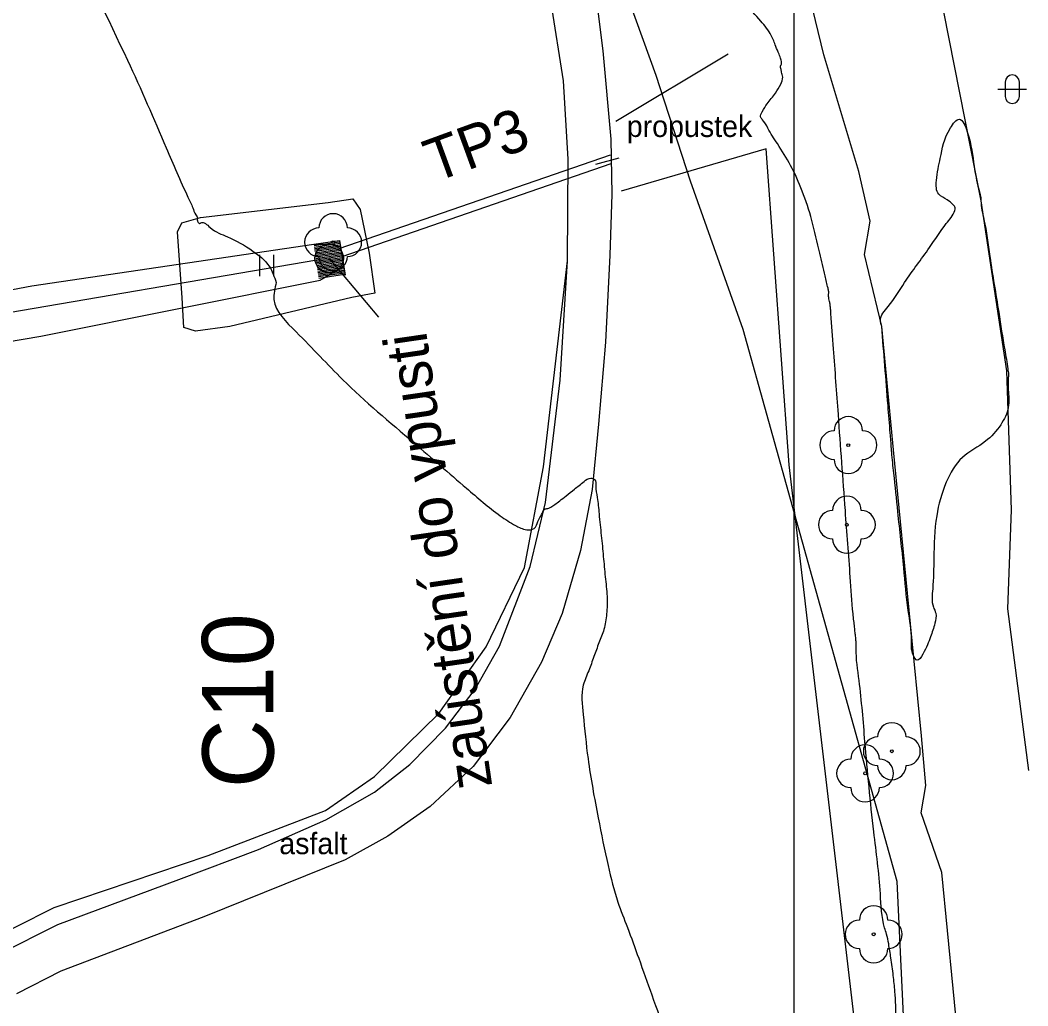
# Model space of a CAD drawing. Extents: x -478102 to -473059, y -1117705 to -1114104.
# Drawn here: x -476236.6 to -476165.9, y -1117084.2 to -1117015 of the extents above; entities that cross this region are included whole.
import ezdxf

# ---------------------------------------------------------------- set-up
doc = ezdxf.new("R2010")
doc.units = 0
for name, color, linetype in [('BodoveZnackySachtaKanalizacni', 7, 'Continuous'), ('cestn___p____kop_n__vrh', 7, 'Continuous'), ('el_vedeni__VN', 7, 'Continuous'), ('HladinaVodnihoToku', 7, 'Continuous'), ('HranaTerennihoUtvaru', 7, 'Continuous'), ('ObPÚ', 7, 'Continuous'), ('OstatniRozhrani', 7, 'Continuous'), ('POLYGONY_SITUACE_PO', 7, 'Continuous'), ('PopisneZnackyKultura', 7, 'Continuous'), ('PopisObjektu', 7, 'Continuous'), ('PopisPovrchu', 7, 'Continuous'), ('RozhraniKultur', 7, 'Continuous'), ('RozhraniVozovky', 7, 'Continuous'), ('TP _navrh', 7, 'Continuous'), ('TP_HS', 7, 'Continuous'), ('Vrstevnice_vedlejsi', 7, 'Continuous'), ('ZnackyStromu', 7, 'Continuous')]:
    doc.layers.add(name, color=color, linetype=linetype)

msp = doc.modelspace()

# ---------------------------------------------------------------- linework, layer by layer
for p, q in [((-476214.237, -1117031.047), (-476195.209, -1117024.475)), ((-476214.041, -1117031.614), (-476195.148, -1117025.088)), ((-476216.022, -1117030.757), (-476214.226, -1117030.492)), ((-476216.022, -1117030.757), (-476214.944, -1117030.754)), ((-476216.022, -1117030.757), (-476214.944, -1117030.754)), ((-476216.008, -1117030.856), (-476214.211, -1117030.591)), ((-476215.993, -1117030.955), (-476214.197, -1117030.69)), ((-476215.978, -1117031.054), (-476214.182, -1117030.789)), ((-476215.964, -1117031.153), (-476214.168, -1117030.888)), ((-476215.949, -1117031.252), (-476214.153, -1117030.986)), ((-476215.935, -1117031.351), (-476214.138, -1117031.085)), ((-476215.92, -1117031.449), (-476214.124, -1117031.184)), ((-476215.905, -1117031.548), (-476214.109, -1117031.283)), ((-476215.891, -1117031.647), (-476214.095, -1117031.382)), ((-476215.876, -1117031.746), (-476214.08, -1117031.481)), ((-476215.862, -1117031.845), (-476214.065, -1117031.58)), ((-476215.847, -1117031.944), (-476214.051, -1117031.679)), ((-476215.832, -1117032.043), (-476214.036, -1117031.778)), ((-476215.818, -1117032.142), (-476214.022, -1117031.877)), ((-476215.803, -1117032.241), (-476214.007, -1117031.976)), ((-476215.789, -1117032.34), (-476213.992, -1117032.075)), ((-476215.774, -1117032.439), (-476213.978, -1117032.174)), ((-476215.759, -1117032.538), (-476213.963, -1117032.273)), ((-476215.745, -1117032.637), (-476213.949, -1117032.371)), ((-476214.944, -1117031.754), (-476211.472, -1117035.864)), ((-476215.73, -1117032.736), (-476213.934, -1117032.47)), ((-476215.715, -1117032.834), (-476213.919, -1117032.569)), ((-476215.701, -1117032.933), (-476213.905, -1117032.668)), ((-476215.686, -1117033.032), (-476213.89, -1117032.767)), ((-476215.672, -1117033.131), (-476213.876, -1117032.866)), ((-476215.571, -1117033.275), (-476214.35, -1117032.58)), ((-476215.571, -1117033.275), (-476214.35, -1117032.58))]:
    msp.add_line(p, q)
at = {"layer": 'BodoveZnackySachtaKanalizacni'}
msp.add_circle((-476214.944, -1117031.754), 1, dxfattribs=at)
msp.add_circle((-476214.944, -1117031.754), 1, dxfattribs=at)
msp.add_circle((-476214.944, -1117031.754), 1, dxfattribs=at)
msp.add_circle((-476214.944, -1117031.754), 1, dxfattribs=at)
at = {"layer": 'cestn___p____kop_n__vrh'}
msp.add_line((-476214.226, -1117030.492), (-476213.83, -1117032.921), dxfattribs=at)
msp.add_lwpolyline([(-476182.335, -1117180.282), (-476602.335, -1117180.282), (-476602.335, -1116586.282), (-476182.335, -1116586.282)], close=True, dxfattribs=at)
at = {"layer": 'el_vedeni__VN'}
for points in [[(-476235.819, -1117033.671), (-476216.022, -1117030.757)], [(-476255.471, -1117037.386), (-476235.819, -1117033.671)], [(-476235.187, -1117037.196), (-476215.571, -1117033.275)], [(-476254.906, -1117040.545), (-476235.187, -1117037.196)]]:
    msp.add_lwpolyline(points, dxfattribs=at)
at = {"layer": 'HladinaVodnihoToku'}
for points in [[(-476230.693, -1116889.189), (-476228.825, -1116902.805), (-476226.997, -1116912.134), (-476222.681, -1116925.337), (-476220.229, -1116932.601), (-476216.175, -1116939.113), (-476212.858, -1116942.625), (-476205.972, -1116953.141), (-476203.252, -1116954.891), (-476199.271, -1116960.088), (-476194.333, -1116968.049), (-476189.738, -1116975.171), (-476186.133, -1116982.38), (-476183.739, -1116986.147), (-476182.486, -1116989.695), (-476180.477, -1116994.376), (-476178.089, -1116997.289), (-476174.589, -1117005.739), (-476171.819, -1117014.439), (-476169.214, -1117027.705), (-476167.401, -1117039.631), (-476167.078, -1117049.404), (-476167.323, -1117056.351), (-476165.871, -1117067.691)], [(-476165.052, -1117135.383), (-476166.552, -1117122.432), (-476167.831, -1117116.835), (-476168.995, -1117106.978), (-476170.029, -1117098.738), (-476170.701, -1117095.145), (-476170.746, -1117087.056), (-476171.949, -1117074.832), (-476173.391, -1117070.652), (-476173.059, -1117068.741), (-476173.366, -1117065.264), (-476174.142, -1117057.395), (-476175.337, -1117045.193), (-476176.15, -1117036.518), (-476177.362, -1117031.476), (-476176.964, -1117029.141), (-476177.777, -1117025.659), (-476180.222, -1117017.465), (-476181.969, -1117010.204)]]:
    msp.add_lwpolyline(points, dxfattribs=at)
at = {"layer": 'HranaTerennihoUtvaru'}
for points in [[(-476186.94, -1117017.41), (-476194.82, -1117022.15)], [(-476178.08, -1117085.22), (-476182.65, -1117046.23), (-476184.28, -1117024.06), (-476194.45, -1117027.03)]]:
    msp.add_lwpolyline(points, dxfattribs=at)
at = {"layer": 'ObPÚ'}
msp.add_lwpolyline([(-476159.5, -1117192.77), (-476224.13, -1117203.13), (-476225.41, -1117191.08), (-476226.67, -1117162.34), (-476231.32, -1117146.23), (-476236.27, -1117130.89), (-476197.93, -1117123.85), (-476173.05, -1117118.52), (-476175.07, -1117075.48), (-476185.89, -1117036.74), (-476189.59, -1117026.33), (-476192, -1117018.92), (-476203.93, -1116985.93)], dxfattribs=at)
at = {"layer": 'OstatniRozhrani'}
msp.add_lwpolyline([(-476194.62, -1117024.71), (-476196.246, -1117025.164)], dxfattribs=at)
at = {"layer": 'POLYGONY_SITUACE_PO'}
msp.add_lwpolyline([(-476215.821, -1117031.882), (-476288.898, -1117044.364)], dxfattribs=at)
at = {"layer": 'PopisneZnackyKultura'}
for p, q in [((-476167.506, -1117019.386), (-476167.506, -1117020.386)), ((-476166.506, -1117019.386), (-476166.506, -1117020.386)), ((-476168.006, -1117019.886), (-476166.006, -1117019.886)), ((-476219.82, -1117032.999), (-476219.82, -1117031.499)), ((-476218.82, -1117032.999), (-476218.82, -1117031.499))]:
    msp.add_line(p, q, dxfattribs=at)
for centre, start, end in [((-476166.998, -1117019.378), 0, 180), ((-476166.998, -1117020.378), 180, 0)]:
    msp.add_arc(centre, 0.5, start, end, dxfattribs=at)
at = {"layer": 'RozhraniKultur'}
msp.add_lwpolyline([(-476225.593, -1117029.883), (-476225.296, -1117029.248), (-476223.977, -1117028.88), (-476215.019, -1117027.833), (-476213.274, -1117027.562), (-476212.764, -1117028.324), (-476212.138, -1117031.392), (-476211.741, -1117034.183), (-476213.357, -1117034.486), (-476221.906, -1117036.536), (-476224.324, -1117036.868), (-476225.145, -1117036.604), (-476225.253, -1117034.523)], close=True, dxfattribs=at)
msp.add_lwpolyline([(-476326.155, -1117118.092), (-476289.536, -1117114.347), (-476268.698, -1117113.377), (-476254.616, -1117112.232), (-476253.368, -1117111.396), (-476254.26, -1117105.118), (-476253.444, -1117098.834), (-476252.052, -1117092.56), (-476249.674, -1117089.102), (-476247.41, -1117085.365), (-476243.552, -1117082.341), (-476239.642, -1117080.005), (-476234.251, -1117077.288), (-476223.428, -1117073.653), (-476215.212, -1117070.499), (-476211.753, -1117068.101), (-476207.257, -1117063.687), (-476203.922, -1117059.007), (-476201.245, -1117053.431), (-476199.908, -1117046.384), (-476198.206, -1117031.932)], dxfattribs=at)
at = {"layer": 'RozhraniVozovky'}
for points in [[(-476196.364, -1117012.13), (-476195.729, -1117017.189), (-476195.176, -1117023.395), (-476195.112, -1117027.233), (-476195.235, -1117031.513), (-476195.559, -1117037.637), (-476196.033, -1117043.394), (-476196.483, -1117047.979), (-476197.306, -1117052.252), (-476198.582, -1117056.674), (-476200.039, -1117060.081), (-476202.244, -1117063.965), (-476204.836, -1117067.407), (-476207.857, -1117070.218), (-476210.834, -1117072.302), (-476213.828, -1117073.953), (-476223.737, -1117077.95), (-476233.774, -1117081.756), (-476236.901, -1117083.35)], [(-476238.115, -1117080.557), (-476233.979, -1117078.501), (-476225.492, -1117075.329), (-476219.895, -1117073.227), (-476215.189, -1117071.158), (-476211.766, -1117069.21), (-476209.272, -1117067.263), (-476206.779, -1117064.716), (-476204.692, -1117061.981), (-476203, -1117058.967), (-476200.833, -1117053.375), (-476199.75, -1117048.873), (-476198.727, -1117040.3), (-476198.206, -1117031.932), (-476198.165, -1117024.787), (-476198.499, -1117019.299), (-476199.36, -1117013.806)]]:
    msp.add_lwpolyline(points, dxfattribs=at)
at = {"layer": 'Vrstevnice_vedlejsi'}
for points in [[(-476316.243, -1116908.48), (-476314.561, -1116908.998), (-476313.123, -1116909.665), (-476311.928, -1116910.479), (-476310.975, -1116911.441), (-476307.447, -1116912.926), (-476301.342, -1116914.935), (-476292.661, -1116917.468), (-476286.431, -1116920.344), (-476282.653, -1116923.565), (-476281.326, -1116927.13), (-476278.825, -1116928.622), (-476275.148, -1116928.043), (-476270.296, -1116925.391), (-476267.359, -1116923.353), (-476266.337, -1116921.926), (-476267.229, -1116921.113), (-476266.831, -1116920.277), (-476265.141, -1116919.419), (-476262.159, -1116918.539), (-476258.731, -1116917.573), (-476254.857, -1116916.522), (-476250.536, -1116915.385), (-476247.506, -1116914.708), (-476245.767, -1116914.49), (-476245.318, -1116914.73), (-476244.967, -1116914.931), (-476244.714, -1116915.09), (-476244.558, -1116915.209), (-476244.297, -1116915.426), (-476243.929, -1116915.74), (-476243.455, -1116916.152), (-476242.992, -1116916.618), (-476242.539, -1116917.137), (-476242.097, -1116917.711), (-476241.648, -1116918.268), (-476241.19, -1116918.809), (-476240.724, -1116919.335), (-476240.357, -1116919.802), (-476240.09, -1116920.212), (-476239.921, -1116920.565), (-476239.776, -1116920.901), (-476239.653, -1116921.22), (-476239.554, -1116921.522), (-476239.275, -1116922.323), (-476238.817, -1116923.622), (-476238.18, -1116925.419), (-476237.671, -1116926.892), (-476237.289, -1116928.04), (-476237.035, -1116928.865), (-476237.012, -1116929.601), (-476237.222, -1116930.251), (-476237.665, -1116930.812), (-476238.042, -1116931.305), (-476238.354, -1116931.728), (-476238.601, -1116932.083), (-476239.32, -1116932.842), (-476240.511, -1116934.008), (-476242.173, -1116935.579), (-476243.89, -1116939.165), (-476245.66, -1116944.767), (-476247.485, -1116952.383), (-476247.667, -1116959.217), (-476246.206, -1116965.267), (-476243.103, -1116970.535), (-476240.745, -1116976.442), (-476239.133, -1116982.988), (-476238.266, -1116990.175), (-476237.639, -1116995.076), (-476237.25, -1116997.694), (-476237.099, -1116998.028), (-476236.956, -1116998.362), (-476236.818, -1116998.698), (-476236.687, -1116999.033), (-476236.643, -1116999.341), (-476236.684, -1116999.621), (-476236.813, -1116999.873), (-476235.592, -1117002.993), (-476233.023, -1117008.983), (-476229.104, -1117017.842), (-476226.381, -1117023.996), (-476224.854, -1117027.447), (-476224.521, -1117028.193), (-476224.304, -1117028.701), (-476224.204, -1117028.973), (-476224.22, -1117029.007), (-476224.213, -1117029.062), (-476224.183, -1117029.137), (-476224.131, -1117029.234), (-476224.075, -1117029.288), (-476224.014, -1117029.297), (-476223.948, -1117029.262), (-476223.307, -1117029.574), (-476222.09, -1117030.231), (-476220.296, -1117031.233), (-476219.154, -1117032.301), (-476218.662, -1117033.435)], [(-476179.724, -1117035.627), (-476179.75, -1117035.303), (-476179.782, -1117035.021), (-476179.82, -1117034.78), (-476179.865, -1117034.582), (-476179.89, -1117034.419), (-476179.894, -1117034.292), (-476179.878, -1117034.199), (-476179.879, -1117034.093), (-476179.896, -1117033.973), (-476179.929, -1117033.839), (-476180.135, -1117032.979), (-476180.515, -1117031.393), (-476181.068, -1117029.081), (-476181.748, -1117027.028), (-476182.554, -1117025.234), (-476183.488, -1117023.699), (-476184.151, -1117022.618), (-476184.543, -1117021.993), (-476184.665, -1117021.823), (-476184.551, -1117021.459), (-476184.202, -1117020.899), (-476183.616, -1117020.145), (-476183.252, -1117019.523), (-476183.11, -1117019.034), (-476183.19, -1117018.678), (-476183.244, -1117018.432), (-476183.271, -1117018.296), (-476183.272, -1117018.269), (-476183.261, -1117018.232), (-476183.237, -1117018.185), (-476183.201, -1117018.126), (-476183.188, -1117018.039), (-476183.199, -1117017.923), (-476183.234, -1117017.779), (-476183.365, -1117017.428), (-476183.592, -1117016.87), (-476183.916, -1117016.106), (-476184.647, -1117015.105), (-476185.785, -1117013.867), (-476187.33, -1117012.392), (-476188.388, -1117011.262), (-476188.958, -1117010.478), (-476189.041, -1117010.039), (-476189.106, -1117009.636), (-476189.153, -1117009.267), (-476189.182, -1117008.935), (-476189.557, -1117008.114), (-476190.278, -1117006.805), (-476191.346, -1117005.008), (-476192.127, -1117003.633), (-476192.621, -1117002.68), (-476192.828, -1117002.148), (-476193.262, -1117001.482), (-476193.923, -1117000.684), (-476194.811, -1116999.752), (-476195.507, -1116998.877), (-476196.011, -1116998.058), (-476196.323, -1116997.295), (-476196.58, -1116996.639), (-476196.782, -1116996.088), (-476196.93, -1116995.644), (-476197.398, -1116994.17), (-476198.187, -1116991.667), (-476199.296, -1116988.134), (-476200.094, -1116985.612), (-476200.58, -1116984.1), (-476200.756, -1116983.599), (-476200.905, -1116983.191), (-476201.028, -1116982.876), (-476201.124, -1116982.653), (-476201.204, -1116982.463), (-476201.268, -1116982.305), (-476201.315, -1116982.181), (-476202.111, -1116980.963), (-476203.654, -1116978.651), (-476205.945, -1116975.246), (-476207.511, -1116972.904), (-476208.351, -1116971.625), (-476208.466, -1116971.41), (-476208.609, -1116971.129), (-476208.78, -1116970.784), (-476208.979, -1116970.373), (-476209.684, -1116969.095), (-476210.895, -1116966.948), (-476212.612, -1116963.934), (-476214.062, -1116961.433), (-476215.245, -1116959.445), (-476216.162, -1116957.97), (-476216.798, -1116956.955), (-476217.154, -1116956.399), (-476217.228, -1116956.303), (-476217.294, -1116956.22), (-476217.349, -1116956.15), (-476217.396, -1116956.094), (-476218.104, -1116955.211), (-476219.474, -1116953.504)], [(-476176.161, -1117036.513), (-476175.718, -1117042.074), (-476175.564, -1117044.01), (-476175.479, -1117045.102), (-476175.461, -1117045.349), (-476175.311, -1117046.825), (-476175.028, -1117049.53), (-476174.614, -1117053.465), (-476174.295, -1117056.457), (-476174.071, -1117058.506), (-476173.943, -1117059.613), (-476173.677, -1117059.948), (-476173.274, -1117059.512), (-476172.734, -1117058.304), (-476172.431, -1117057.352), (-476172.366, -1117056.656), (-476172.538, -1117056.216), (-476172.585, -1117054.93), (-476172.507, -1117052.798), (-476172.304, -1117049.82), (-476171.633, -1117047.459), (-476170.492, -1117045.715), (-476168.883, -1117044.587), (-476167.811, -1117043.42), (-476167.276, -1117042.212), (-476167.277, -1117040.965), (-476167.282, -1117040.123), (-476167.288, -1117039.686), (-476167.298, -1117039.655), (-476167.306, -1117039.615), (-476167.313, -1117039.564), (-476167.319, -1117039.504), (-476167.531, -1117038.16), (-476167.948, -1117035.533), (-476168.572, -1117031.623), (-476168.988, -1117029.013), (-476169.197, -1117027.703), (-476169.197, -1117027.693), (-476169.357, -1117026.885), (-476169.677, -1117025.278), (-476170.156, -1117022.874), (-476170.711, -1117021.98), (-476171.342, -1117022.599), (-476172.05, -1117024.729), (-476172.323, -1117026.279), (-476172.161, -1117027.249), (-476171.565, -1117027.64), (-476171.177, -1117027.959), (-476170.999, -1117028.206), (-476171.029, -1117028.383), (-476171.632, -1117029.313), (-476172.807, -1117030.997), (-476174.556, -1117033.436), (-476175.706, -1117035.133), (-476176.257, -1117036.087), (-476176.161, -1117036.513)], [(-476218.662, -1117033.435), (-476218.822, -1117034.635), (-476217.263, -1117036.911), (-476213.986, -1117040.265), (-476208.992, -1117044.695), (-476205.309, -1117047.877), (-476202.938, -1117049.809), (-476201.877, -1117050.493), (-476201.083, -1117050.788), (-476200.555, -1117050.695), (-476200.293, -1117050.212), (-476200.099, -1117049.847), (-476199.974, -1117049.597), (-476199.917, -1117049.464), (-476199.835, -1117049.37), (-476199.726, -1117049.313), (-476199.592, -1117049.295), (-476199.387, -1117049.198), (-476199.112, -1117049.021), (-476198.765, -1117048.765), (-476198.307, -1117048.409), (-476197.736, -1117047.953), (-476197.054, -1117047.397), (-476196.575, -1117047.173), (-476196.299, -1117047.28), (-476196.227, -1117047.719), (-476196.128, -1117048.519), (-476196.001, -1117049.68), (-476195.846, -1117051.202), (-476195.702, -1117052.674), (-476195.567, -1117054.097), (-476195.442, -1117055.471), (-476195.474, -1117056.701), (-476195.663, -1117057.787), (-476196.008, -1117058.731), (-476196.365, -1117059.696), (-476196.731, -1117060.685), (-476197.109, -1117061.695), (-476197.123, -1117063.752), (-476196.775, -1117066.855), (-476196.063, -1117071.005), (-476195.366, -1117074.361), (-476194.682, -1117076.923), (-476194.013, -1117078.692), (-476193.219, -1117080.86), (-476192.302, -1117083.427), (-476191.26, -1117086.392), (-476189.817, -1117090.625), (-476187.973, -1117096.125), (-476185.729, -1117102.894), (-476183.735, -1117108.045), (-476181.992, -1117111.578), (-476180.498, -1117113.494), (-476178.823, -1117115.088), (-476176.965, -1117116.361), (-476174.925, -1117117.312), (-476173.551, -1117118.042), (-476172.843, -1117118.55), (-476172.8, -1117118.837), (-476172.731, -1117119.351), (-476172.637, -1117120.093), (-476172.517, -1117121.062), (-476172.381, -1117123.052), (-476172.229, -1117126.063), (-476172.059, -1117130.096), (-476171.954, -1117132.864), (-476171.913, -1117134.367), (-476171.937, -1117134.606), (-476172.55, -1117135.185), (-476173.752, -1117136.105), (-476175.544, -1117137.365), (-476176.609, -1117138.711), (-476176.875, -1117139.506)], [(-476167.154, -1117137.424), (-476167.161, -1117137.225), (-476167.247, -1117136.247), (-476167.406, -1117134.768), (-476167.64, -1117132.789), (-476168.012, -1117130.045), (-476168.521, -1117126.535), (-476169.167, -1117122.259), (-476169.669, -1117119.115), (-476170.025, -1117117.1), (-476170.236, -1117116.217), (-476170.442, -1117115.129), (-476170.643, -1117113.838), (-476170.838, -1117112.343), (-476171.127, -1117110.728), (-476171.51, -1117108.993), (-476171.987, -1117107.138), (-476172.343, -1117105.532), (-476172.58, -1117104.177), (-476172.697, -1117103.072), (-476172.807, -1117102.176), (-476172.909, -1117101.489), (-476173.004, -1117101.011), (-476173.299, -1117099.062), (-476173.794, -1117095.642), (-476174.488, -1117090.75), (-476174.951, -1117087.207), (-476175.181, -1117085.013), (-476175.18, -1117084.167), (-476175.236, -1117083.188), (-476175.348, -1117082.077), (-476175.517, -1117080.833), (-476175.674, -1117079.86), (-476175.821, -1117079.16), (-476175.956, -1117078.731), (-476176.254, -1117076.34), (-476176.715, -1117071.985), (-476177.338, -1117065.667), (-476177.752, -1117061.381), (-476177.957, -1117059.126), (-476177.954, -1117058.902), (-476177.964, -1117058.642), (-476177.989, -1117058.344), (-476178.028, -1117058.009), (-476178.071, -1117057.621), (-476178.119, -1117057.181), (-476178.171, -1117056.687), (-476178.37, -1117054.109), (-476178.715, -1117049.446), (-476179.207, -1117042.699), (-476179.543, -1117038.092), (-476179.724, -1117035.627)]]:
    msp.add_spline(points, degree=3, dxfattribs=at)
at = {"layer": 'ZnackyStromu'}
for centre in [(-476214.667, -1117030.614), (-476178.506, -1117044.853), (-476178.606, -1117050.437), (-476175.452, -1117066.335), (-476177.329, -1117067.885), (-476176.727, -1117079.181)]:
    msp.add_circle(centre, 0.1, dxfattribs=at)
for centre, start, end in [((-476214.667, -1117029.614), 0, 180), ((-476215.667, -1117030.614), 90, 270), ((-476213.667, -1117030.614), 270, 90), ((-476214.667, -1117031.614), 180, 0), ((-476178.506, -1117043.853), 0, 180), ((-476179.506, -1117044.853), 90, 270), ((-476177.506, -1117044.853), 270, 90), ((-476178.506, -1117045.853), 180, 0), ((-476178.606, -1117049.437), 0, 180), ((-476179.606, -1117050.437), 90, 270), ((-476177.606, -1117050.437), 270, 90), ((-476178.606, -1117051.437), 180, 0), ((-476175.452, -1117065.335), 0, 180), ((-476176.452, -1117066.335), 90, 270), ((-476174.452, -1117066.335), 270, 90), ((-476177.329, -1117066.885), 0, 180), ((-476178.329, -1117067.885), 90, 270), ((-476176.329, -1117067.885), 270, 90), ((-476175.452, -1117067.335), 180, 0), ((-476177.329, -1117068.885), 180, 0), ((-476176.727, -1117078.181), 0, 180), ((-476177.727, -1117079.181), 90, 270), ((-476175.727, -1117079.181), 270, 90), ((-476176.727, -1117080.181), 180, 0)]:
    msp.add_arc(centre, 1, start, end, dxfattribs=at)

# ---------------------------------------------------------------- texts
at = {"layer": 'PopisObjektu'}
msp.add_text('propustek', height=1.5, dxfattribs=at).set_placement((-476194.057, -1117023.23))
at = {"layer": 'PopisPovrchu'}
msp.add_text('asfalt', height=1.5, dxfattribs=at).set_placement((-476218.448, -1117073.559))
at = {"layer": 'TP _navrh'}
for s, rotation, p in [('TP3', 20.06066, (-476207.571, -1117026.44)), ('zaústění do vpusti', 98.28402, (-476203.492, -1117068.783))]:
    msp.add_text(s, height=3, rotation=rotation, dxfattribs=at).set_placement(p)
at = {"layer": 'TP_HS'}
msp.add_text('C10', height=5, rotation=90.22451, dxfattribs=at).set_placement((-476218.834, -1117068.911))

doc.saveas('drawing.dxf')
